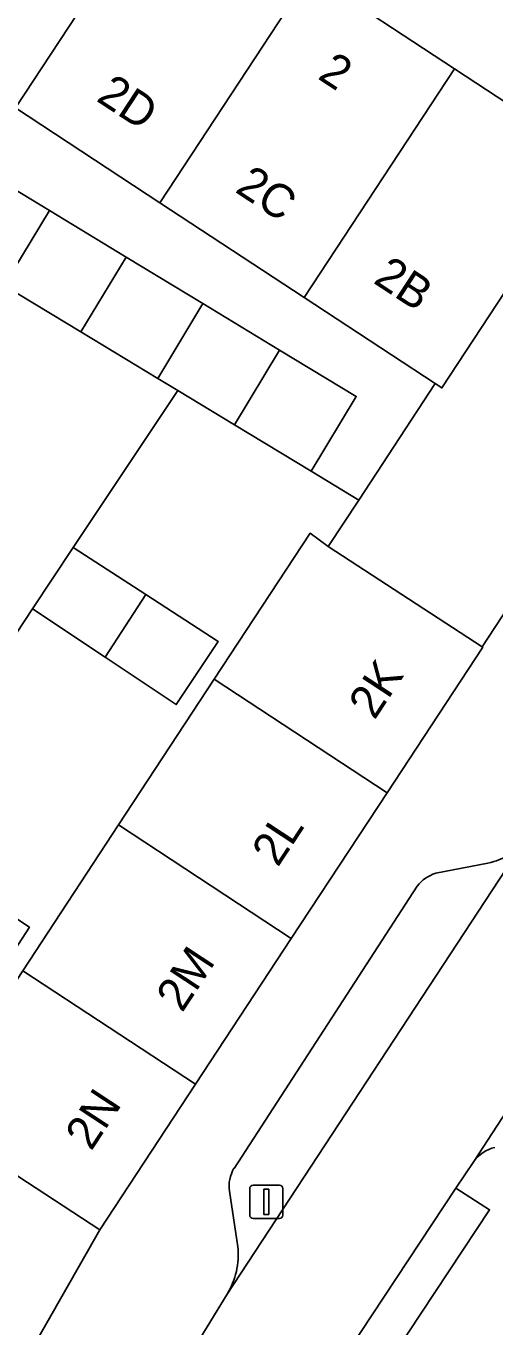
# Model space of a CAD drawing. Extents: x 159279 to 160377, y 384531 to 385888.
# Drawn here: x 159646.49 to 159660.55, y 385039.9 to 385078.89 of the extents above; entities that cross this region are included whole.
import ezdxf

# ---------------------------------------------------------------- set-up
doc = ezdxf.new("R2010")
doc.units = 0
for name, color, linetype in [('IMGEO_Erf', 7, 'Continuous'), ('IMGEO_Hek', 7, 'Continuous'), ('IMGEO_Lichtmast', 7, 'Continuous'), ('IMGEO_Pand', 7, 'Continuous'), ('IMGEO_Pand_nummerreeks', 7, 'Continuous'), ('IMGEO_Parkeervlak_open', 7, 'Continuous'), ('IMGEO_Rijbaan_lokaal_open', 7, 'Continuous'), ('IMGEO_Voetpad_open', 7, 'Continuous')]:
    doc.layers.add(name, color=color, linetype=linetype)

msp = doc.modelspace()

# ---------------------------------------------------------------- linework, layer by layer
at = {"layer": 'IMGEO_Erf'}
for points in [[(159644.898, 385074.746), (159647.197, 385073.354), (159649.496, 385071.962), (159651.795, 385070.569), (159654.094, 385069.177), (159656.393, 385067.785), (159655.036, 385065.544), (159656.465, 385064.679), (159658.754, 385068.175), (159654.834, 385070.75), (159650.506, 385073.593), (159646.179, 385076.435)], [(159642.257, 385054.712), (159646.683, 385061.425), (159647.903, 385063.257), (159651.038, 385067.965), (159650.438, 385068.329), (159648.139, 385069.721), (159645.84, 385071.113)], [(159646.054, 385038.17), (159648.699, 385042.808), (159643.519, 385046.2)]]:
    msp.add_lwpolyline(points, dxfattribs=at)
msp.add_lwpolyline([(159652.132, 385059.313), (159655.005, 385063.687), (159655.553, 385063.286), (159656.465, 385064.679), (159655.036, 385065.544), (159652.737, 385066.936), (159651.038, 385067.965), (159647.903, 385063.257), (159650.08, 385061.848), (159652.256, 385060.438), (159650.994, 385058.554), (159648.865, 385059.972), (159646.683, 385061.425), (159642.257, 385054.712), (159644.426, 385053.296), (159646.594, 385051.88), (159645.394, 385050.042), (159643.225, 385051.458), (159641.057, 385052.874), (159638.742, 385049.328), (159643.519, 385046.2), (159646.394, 385050.578), (159649.263, 385054.945)], close=True, dxfattribs=at)
at = {"layer": 'IMGEO_Hek'}
for points in [[(159647.903, 385063.257), (159651.038, 385067.965)], [(159655.036, 385065.544), (159656.465, 385064.679)], [(159642.257, 385054.712), (159646.683, 385061.425)]]:
    msp.add_lwpolyline(points, dxfattribs=at)
at = {"layer": 'IMGEO_Lichtmast'}
for p, q in [((159653.197, 385043.251), (159653.197, 385044.051)), ((159653.197, 385044.051), (159653.197, 385043.251)), ((159653.297, 385044.151), (159654.087, 385044.151)), ((159654.087, 385044.151), (159653.297, 385044.151)), ((159654.187, 385044.051), (159654.187, 385043.251)), ((159654.187, 385043.251), (159654.187, 385044.051)), ((159654.087, 385043.151), (159653.297, 385043.151)), ((159653.297, 385043.151), (159654.087, 385043.151))]:
    msp.add_line(p, q, dxfattribs=at)
msp.add_lwpolyline([(159653.617, 385044.026), (159653.767, 385044.026), (159653.767, 385043.276), (159653.617, 385043.276), (159653.617, 385044.026)], dxfattribs=at)
for centre, start, end in [((159653.297, 385044.051), 90, 180), ((159653.297, 385044.051), 90, 180), ((159654.087, 385044.051), 0, 90), ((159654.087, 385044.051), 360, 90), ((159653.297, 385043.251), 180, 270), ((159653.297, 385043.251), 180, 270), ((159654.087, 385043.251), 270, 0), ((159654.087, 385043.251), 270, 0)]:
    msp.add_arc(centre, 0.1, start, end, dxfattribs=at)
at = {"layer": 'IMGEO_Pand'}
for points in [[(159650.682, 385083.29), (159646.355, 385086.133), (159641.852, 385079.278), (159646.179, 385076.435)], [(159655.009, 385080.447), (159650.682, 385083.29), (159646.179, 385076.435), (159650.506, 385073.593)], [(159659.337, 385077.604), (159655.009, 385080.447), (159650.506, 385073.593), (159654.834, 385070.75)], [(159663.46, 385074.896), (159659.337, 385077.604), (159654.834, 385070.75), (159658.754, 385068.175), (159658.958, 385068.041)], [(159667.991, 385071.919), (159663.46, 385074.896), (159658.958, 385068.041), (159658.754, 385068.175), (159656.465, 385064.679), (159655.553, 385063.286), (159660.163, 385060.285), (159664.458, 385066.832), (159664.59, 385066.751)], [(159647.197, 385073.354), (159644.898, 385074.746), (159643.447, 385072.563), (159645.84, 385071.113)], [(159649.496, 385071.962), (159647.197, 385073.354), (159645.84, 385071.113), (159648.139, 385069.721)], [(159651.795, 385070.569), (159649.496, 385071.962), (159648.139, 385069.721), (159650.438, 385068.329)], [(159654.094, 385069.177), (159651.795, 385070.569), (159650.438, 385068.329), (159651.038, 385067.965), (159652.737, 385066.936)], [(159656.393, 385067.785), (159654.094, 385069.177), (159652.737, 385066.936), (159655.036, 385065.544)], [(159660.184, 385060.272), (159660.163, 385060.285), (159655.553, 385063.286), (159655.005, 385063.687), (159652.132, 385059.313), (159657.313, 385055.906)], [(159650.08, 385061.848), (159647.903, 385063.257), (159646.683, 385061.425), (159648.865, 385059.972)], [(159652.256, 385060.438), (159650.08, 385061.848), (159648.865, 385059.972), (159650.994, 385058.554)], [(159657.313, 385055.906), (159652.132, 385059.313), (159649.263, 385054.945), (159654.442, 385051.54)], [(159654.442, 385051.54), (159649.263, 385054.945), (159646.394, 385050.578), (159651.57, 385047.174)], [(159646.594, 385051.88), (159644.426, 385053.296), (159643.225, 385051.458), (159645.394, 385050.042)], [(159651.57, 385047.174), (159646.394, 385050.578), (159643.519, 385046.2), (159648.699, 385042.808)]]:
    msp.add_lwpolyline(points, close=True, dxfattribs=at)
at = {"layer": 'IMGEO_Parkeervlak_open'}
for points in [[(159652.518, 385040.886), (159661.5, 385054.568)], [(159660.34, 385053.804), (159658.772, 385053.5)], [(159658.22, 385053.113), (159652.726, 385044.655)], [(159665.446, 385051.466), (159665.234, 385052.455), (159665.274, 385053.079), (159659.919, 385044.859)], [(159652.587, 385043.971), (159652.842, 385042.302)]]:
    msp.add_lwpolyline(points, dxfattribs=at)
msp.add_lwpolyline([(159659.378, 385044.063), (159651.154, 385031.619), (159645.527, 385023.106), (159646.52, 385022.448), (159660.387, 385043.416)], close=True, dxfattribs=at)
for centre, radius, start, end in [((159659.979, 385055.614), 1.846, 281.27, 325.4695), ((159659.125, 385052.41), 1.146, 107.9309, 142.1367), ((159660.783, 385044.252), 1.056, 102.7644, 144.9086), ((159653.666, 385044.108), 1.088, 149.8024, 187.2235), ((159650.59, 385042.072), 2.263, 328.3946, 5.8291)]:
    msp.add_arc(centre, radius, start, end, dxfattribs=at)
at = {"layer": 'IMGEO_Rijbaan_lokaal_open'}
msp.add_lwpolyline([(159661.5, 385054.568), (159652.518, 385040.886), (159646.935, 385031.761), (159644.447, 385027.972), (159642.414, 385024.877), (159640.705, 385022.275), (159640.084, 385021.339), (159639.191, 385019.992), (159639.064, 385019.858), (159638.986, 385019.776), (159641.952, 385017.841), (159642.182, 385018.227), (159645.527, 385023.106), (159651.154, 385031.619), (159659.378, 385044.063), (159659.919, 385044.859), (159665.274, 385053.079)], dxfattribs=at)
at = {"layer": 'IMGEO_Voetpad_open'}
for points in [[(159646.355, 385086.133), (159650.682, 385083.29), (159655.009, 385080.447), (159659.337, 385077.604), (159663.46, 385074.896), (159667.991, 385071.919), (159696.929, 385115.976), (159690.82, 385119.987), (159684.71, 385123.999), (159678.601, 385128.01), (159672.491, 385132.021), (159666.382, 385136.032), (159660.451, 385139.926), (159654.163, 385144.055), (159646.071, 385149.369)], [(159696.929, 385115.976), (159667.991, 385071.919), (159664.59, 385066.751), (159664.458, 385066.832), (159660.163, 385060.285), (159660.184, 385060.272), (159657.313, 385055.906), (159654.442, 385051.54), (159651.57, 385047.174), (159648.699, 385042.808), (159646.054, 385038.17), (159646.904, 385037.679), (159629.213, 385010.854)], [(159658.772, 385053.5), (159660.34, 385053.804)], [(159652.726, 385044.655), (159658.22, 385053.113)], [(159659.919, 385044.859), (159659.378, 385044.063), (159660.387, 385043.416), (159646.52, 385022.448), (159645.527, 385023.106), (159642.182, 385018.227), (159641.952, 385017.841), (159641.907, 385017.692), (159641.875, 385017.539), (159641.856, 385017.384), (159641.852, 385017.228), (159641.862, 385017.072), (159641.886, 385016.918), (159641.968, 385016.637), (159642.251, 385015.665)], [(159652.842, 385042.302), (159652.587, 385043.971)], [(159645.502, 385032.699), (159646.935, 385031.761), (159652.518, 385040.886)]]:
    msp.add_lwpolyline(points, dxfattribs=at)
for centre, radius, start, end in [((159659.979, 385055.614), 1.846, 281.27, 325.4695), ((159659.125, 385052.41), 1.146, 107.9309, 142.1367), ((159660.783, 385044.252), 1.056, 102.7644, 144.9086), ((159653.666, 385044.108), 1.088, 149.8024, 187.2235), ((159650.59, 385042.072), 2.263, 328.3946, 5.8291)]:
    msp.add_arc(centre, radius, start, end, dxfattribs=at)

# ---------------------------------------------------------------- texts
at = {"layer": 'IMGEO_Pand_nummerreeks'}
for s, rotation, p in [('2', 326.6997, (159655.203, 385077.328)), ('2D', 326.7054, (159648.565, 385076.663)), ('2C', 326.6997, (159652.725, 385073.931)), ('2B', 326.6997, (159656.869, 385071.208)), ('2K', 56.6713, (159656.939, 385058.067)), ('2L', 56.6713, (159654.038, 385053.655)), ('2M', 56.6655, (159651.171, 385049.296)), ('2N', 56.6713, (159648.444, 385045.15))]:
    msp.add_text(s, height=1, rotation=rotation, dxfattribs=at).set_placement(p)

doc.saveas('drawing.dxf')
